AutomationDirect Productivity Suite project: L7P (software 3.11.0 (26))
author: fguedez
Rung notation: left to right = series (deeper-indented lines continue the line above), [a | b] = parallel branches, -- = plain wire, BOX.Pin = further input of the box above; 'quoted' = tag name, ? = field left empty; instruction and field names as stored in the project; options that are off are not listed.

HARDWARE
  EtherNet/IP device: Generic Client "SS2 EIP"
  Base 1 (5 slots)
    slot 0: P2-550

TAGS  (name : type @system ID = initial value)
  Dummy1 : Int16 @S16-000001
  'EC Done' : Boolean @C-000183
  'Error Counter' : Int32 @S32-000129
  'IC Done' : Boolean @C-000214
  'Interlock Counter' : Int32 @S32-000131
  'ip0001 Servo Alarm' : Int16 @S16-000021
  'ip0001N2 Servo Alarm' : Int16 @S16-000029
  'IP0009 Monitoring Parameter' : Int32 @S32-000139
  'IP0009N2 Monitoring Parameter' : Int32 @S32-000165
  'IP0010 Monitoring Parameter' : Int32 @S32-000140
  'IP0010N2 Monitoring Parameter' : Int32 @S32-000166
  'IP0011 Monitoring Parameter' : Int32 @S32-000141
  'IP0011N2 Monitoring Parameter' : Int32 @S32-000167
  'IP0012 Monitoring Parameter' : Int32 @S32-000142
  'IP0012N2 Monitoring Parameter' : Int32 @S32-000168
  'IP0013 Monitoring Parameter' : Int32 @S32-000177
  'IP0013N2 Monitoring Parameter' : Int32 @S32-000183
  'IP0025 Mapping Parameter' : Int32 @S32-000085
  'IP0025N2 Mapping Parameter' : Int32 @S32-000169
  'IP0026 Mapping Parameter' : Int32 @S32-000086
  'IP0026N2 Mapping Parameter' : Int32 @S32-000170
  'IP0027 Mapping Parameter' : Int32 @S32-000087
  'IP0027N2 Mapping Parameter' : Int32 @S32-000171
  'IP0028 Mapping Parameter' : Int32 @S32-000088
  'IP0028N2 Mapping Parameter' : Int32 @S32-000172
  'ip0046 DO Status' : Int16 @S16-000022
  'ip0046N2 DO Status' : Int16 @S16-000030
  'IP10000 Position FB' : Int32 @S32-000089
  'IP10000N2 Position Feedback' : Int32 @S32-000187
  'IP10007 Speed FB' : Int32 @S32-000091
  'IP10007N2 SpeedFeedback' : Int32 @S32-000188
  'IP10018 Z Phase offset' : Int32 @S32-000184
  'IP10018N2 Z Phase offset' : Int32 @S32-000189
  'IP10039 DI Status integrated' : Int32 @S32-000180
  'IP10039N2 DI Status integrated' : Int32 @S32-000190
  'IP10054 Torque FB' : Int32 @S32-000094
  'IP10054N2 Torque Feedback' : Int32 @S32-000191
  'ip5123 PR Status' : Int16 @S16-000028
  'ip5123N2 PR Status' : Int16 @S16-000031
  'Modbus RTU' : Boolean @C-000266
  'Modbus TCP' : Boolean @C-000304
  'OP0029 Mapping Parameter' : Int32 @S32-000099
  'OP0029N2 Mapping Parameter' : Int32 @S32-000173
  'OP0030 Mapping Parameter' : Int32 @S32-000100
  'OP0030N2 Mapping Parameter' : Int32 @S32-000174
  'OP0031 Mapping Parameter' : Int32 @S32-000101
  'OP0031N2 Mapping Parameter' : Int32 @S32-000175
  'OP0032 Mapping Parameter' : Int32 @S32-000102
  'OP0032N2 Mapping Parameter' : Int32 @S32-000176
  'OP1011 Int Speed CMD 3' : Int32 @S32-000230
  'OP1011N2 Int Speed CMD3' : Int32 @S32-000193
  'oP4007 Virtual Digital Inputs' : Int16 @S16-000007
  'oP4007N2 Virtual Digital Inputs' : Int16 @S16-000033
  'oP5112 PR Path Target' : Uint16 @US16-000013
  'oP5112N2 PR Path Target' : Int16 @S16-000034
  'oP5122 PR Path Trigger' : Uint16 @US16-000012
  'oP5122N2 PR Path Trigger' : Int16 @S16-000035
  SS2DataIn : Array[16] of Int32 @AR1S32-000001
    // element 1.2.11: warning
    // element 1.2.10: early warning for motor overload
    // element 1.2.9: homing completed
    // element 1.2.1: servo ready
    // element 1.2.2: servo activated
    // element 1.2.3: zero speed detection
    // element 1.0: Z Offset
    // element 1.2.4: target speed reached
    // element 2.0: Position Feedback
    // element 1.2.5: target position reached
    // element 1.2.6: torque limit activated
    // element 3.0: Speed Feedback
    // element 1.2.7: servo alarm
    // element 4.0: Torque Feedback
    // element 1.2.8: magnetic brake control output
    // element 5.0: DO Status
    // element 6.0: IP0025 Monitoring Parameter
    // element 7.0: IP0026 Monitoring Parameter
    // element 8.0: IP0027 Monitoring Parameter
    // element 9.0: IP0028 Monitoring Parameter
  SS2DataOut : Array[16] of Int32 @AR1S32-000002
    // element 1.1.3: PR[1]/Torque[0] sel
    // element 1.0: OP0029 Monitoring Parameter
    // element 2.0: OP0030 Monitoring Parameter
    // element 3.0: OP0031 Monitoring Parameter
    // element 4.0: OP0032 Monitoring Parameter
    // element 1.1.1: Servo Enable bit
  'Success Counter' : Int32 @S32-000130
  'Success Done' : Boolean @C-000111
  TimedC : Boolean @C-000225
  ALARM : Boolean @C-000430
  BRAKE : Boolean @C-000431
  INPOS1 : Boolean @C-000432
  INSPD : Boolean @C-000433
  READY : Boolean @C-000434
  TGON : Boolean @C-000435
  TLMT : Boolean @C-000436
  VLMT : Boolean @C-000437
  WARN : Boolean @C-000438
  ZSPD : Boolean @C-000439
  A_RST : Boolean @C-000440
  EMG : Boolean @C-000441
  GAIN2 : Boolean @C-000442
  HOME : Boolean @C-000443
  HSTART : Boolean @C-000444
  ISEL0 : Boolean @C-000445
  ISEL1 : Boolean @C-000446
  ISEL2 : Boolean @C-000447
  ISEL3 : Boolean @C-000448
  ISEL4 : Boolean @C-000449
  ISEL5 : Boolean @C-000450
  MODE : Boolean @C-000451
  N_CL : Boolean @C-000452
  NOT : Boolean @C-000453
  P_CL : Boolean @C-000454
  PAUSE : Boolean @C-000455
  PCON : Boolean @C-000456
  POT : Boolean @C-000457
  REGT : Boolean @C-000458
  RESERVED : Boolean @C-000459
  SPD1 : Boolean @C-000460
  SPD2 : Boolean @C-000461
  SPD3 : Boolean @C-000462
  START : Boolean @C-000463
  STOP : Boolean @C-000464
  SV_ON : Boolean @C-000465
  'Actual Velocity' : Int16 @S16-000036
  'Velocity Command' : Int16 @S16-000037
  'First Time' : Boolean @C-000516
  'Counter Setpoint' : Int32 @S32-000231
  'L7CA Velocity' : Boolean @C-000517
  'Actual Position' : Int32 @S32-000232
  'L7CA Index' : Boolean @C-000518
  Index : Int32 @S32-000233
  N1ALARM : Boolean @C-000577
  N1BRAKE : Boolean @C-000578
  N1INPOS1 : Boolean @C-000579
  N1INSPD : Boolean @C-000580
  N1READY : Boolean @C-000581
  N1TGON : Boolean @C-000582
  N1TLMT : Boolean @C-000583
  N1VLMT : Boolean @C-000584
  N1WARN : Boolean @C-000585
  N1ZSPD : Boolean @C-000586
  N1A_RST : Boolean @C-000587
  N1EMG : Boolean @C-000588
  N1GAIN2 : Boolean @C-000589
  N1HOME : Boolean @C-000590
  N1HSTART : Boolean @C-000591
  N1ISEL0 : Boolean @C-000592
  N1ISEL1 : Boolean @C-000593
  N1ISEL2 : Boolean @C-000594
  N1ISEL3 : Boolean @C-000595
  N1ISEL4 : Boolean @C-000596
  N1ISEL5 : Boolean @C-000597
  N1MODE : Boolean @C-000598
  N1N_CL : Boolean @C-000599
  N1NOT : Boolean @C-000600
  N1P_CL : Boolean @C-000601
  N1PAUSE : Boolean @C-000602
  N1PCON : Boolean @C-000603
  N1POT : Boolean @C-000604
  N1REGT : Boolean @C-000605
  N1RESERVED : Boolean @C-000606
  N1SPD1 : Boolean @C-000607
  N1SPD2 : Boolean @C-000608
  N1SPD3 : Boolean @C-000609
  N1START : Boolean @C-000610
  N1STOP : Boolean @C-000611
  N1SV_ON : Boolean @C-000612
  'N1Actual Velocity' : Int16 @S16-000042
  'N1Velocity Command' : Int16 @S16-000038
  N2ALARM : Boolean @C-000613
  N2BRAKE : Boolean @C-000614
  N2INPOS1 : Boolean @C-000615
  N2INSPD : Boolean @C-000616
  N2READY : Boolean @C-000617
  N2TGON : Boolean @C-000618
  N2TLMT : Boolean @C-000619
  N2VLMT : Boolean @C-000620
  N2WARN : Boolean @C-000621
  N2ZSPD : Boolean @C-000622
  N2A_RST : Boolean @C-000623
  N2EMG : Boolean @C-000624
  N2GAIN2 : Boolean @C-000625
  N2HOME : Boolean @C-000626
  N2HSTART : Boolean @C-000627
  N2ISEL0 : Boolean @C-000628
  N2ISEL1 : Boolean @C-000629
  N2ISEL2 : Boolean @C-000630
  N2ISEL3 : Boolean @C-000631
  N2ISEL4 : Boolean @C-000632
  N2ISEL5 : Boolean @C-000633
  N2MODE : Boolean @C-000634
  N2N_CL : Boolean @C-000635
  N2NOT : Boolean @C-000636
  N2P_CL : Boolean @C-000637
  N2PAUSE : Boolean @C-000638
  N2PCON : Boolean @C-000639
  N2POT : Boolean @C-000640
  N2REGT : Boolean @C-000641
  N2RESERVED : Boolean @C-000642
  N2SPD1 : Boolean @C-000643
  N2SPD2 : Boolean @C-000644
  N2SPD3 : Boolean @C-000645
  N2START : Boolean @C-000646
  N2STOP : Boolean @C-000647
  N2SV_ON : Boolean @C-000648
  'N2Actual Velocity' : Int16 @S16-000039
  'N2Velocity Command' : Int16 @S16-000040
  'L7P Velocity' : Boolean @C-000649
  'L7P Index' : Boolean @C-000650
  'N1Actual Position' : Int32 @S32-000235
  Index2 : Int16 @S16-000041
  'N2Actual Position' : Int32 @S32-000236

SYSTEM TAGS USED OR MAPPED TO MODBUS
  'L7PN1 Node Read' : MRX @SSTRUC-000048  // System Structure for Modbus Read
  'L7PN1 Node Write' : MWX @SSTRUC-000049  // System Structure for Modbus Write
  'L7PN1 Node Write2' : MWX @SSTRUC-000051  // System Structure for Modbus Write
  'L7PN2 Node Read' : MRX @SSTRUC-000053  // System Structure for Modbus Read
  'L7PN2 Node Write' : MWX @SSTRUC-000054  // System Structure for Modbus Write
  'L7PN2 Node Read2' : MRX @SSTRUC-000055  // System Structure for Modbus Read
  'L7PN2 Node Write2' : MWX @SSTRUC-000056  // System Structure for Modbus Write
  'L7PN2 Node Write3' : MWX @SSTRUC-000057  // System Structure for Modbus Write
  'L7PN1 Node Read2' : MRX @SSTRUC-000058  // System Structure for Modbus Read
  'L7PN1 Node Write3' : MWX @SSTRUC-000059  // System Structure for Modbus Write

TASK Main  (Run Every Scan)
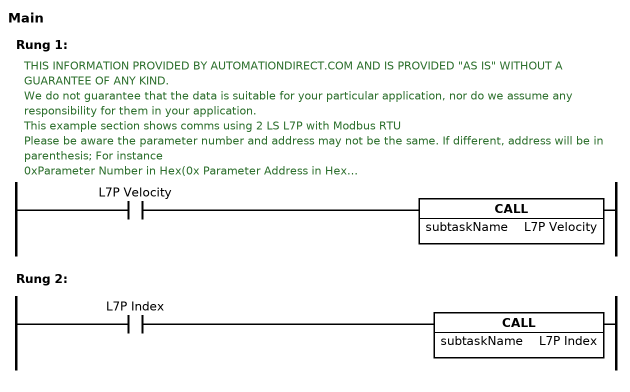
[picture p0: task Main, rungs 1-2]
Rung 1:
  // THIS INFORMATION PROVIDED BY AUTOMATIONDIRECT.COM AND IS PROVIDED "AS IS" WITHOUT A GUARANTEE OF ANY KIND.
  // We do not guarantee that the data is suitable for your particular application, nor do we assume any responsibility for them in your application.
  // This example section shows comms using 2 LS L7P with Modbus RTU
  // Please be aware the parameter number and address may not be the same. If different, address will be in parenthesis; For instance
  // 0xParameter Number in Hex(0x Parameter Address in Hex)
  // Address values are in hexadecimal
  // Please verify addresses in the LS L7P Manual
  NO('L7P Velocity') CALL('L7P Velocity')
Rung 2:
  NO('L7P Index') CALL('L7P Index')

TASK 'L7P Velocity'  (Run When Called)
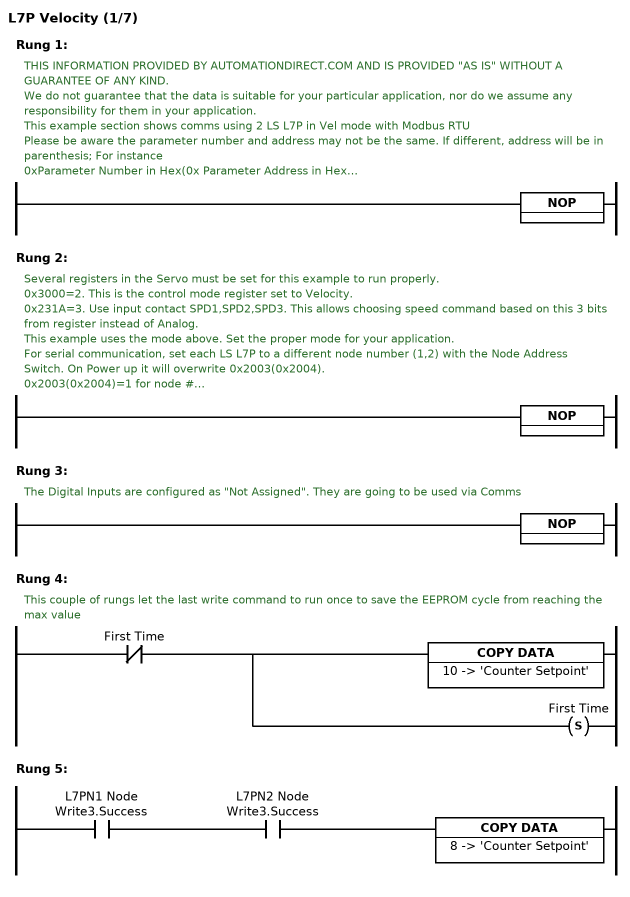
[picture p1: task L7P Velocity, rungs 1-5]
Rung 1:
  // THIS INFORMATION PROVIDED BY AUTOMATIONDIRECT.COM AND IS PROVIDED "AS IS" WITHOUT A GUARANTEE OF ANY KIND.
  // We do not guarantee that the data is suitable for your particular application, nor do we assume any responsibility for them in your application.
  // This example section shows comms using 2 LS L7P in Vel mode with Modbus RTU
  // Please be aware the parameter number and address may not be the same. If different, address will be in parenthesis; For instance
  // 0xParameter Number in Hex(0x Parameter Address in Hex)
  // Address values are in hexadecimal
  // Please verify addresses in the LS L7P Manual
  NOP()
Rung 2:
  // Several registers in the Servo must be set for this example to run properly.
  // 0x3000=2. This is the control mode register set to Velocity.
  // 0x231A=3. Use input contact SPD1,SPD2,SPD3. This allows choosing speed command based on this 3 bits from register instead of Analog.
  // This example uses the mode above. Set the proper mode for your application.
  // For serial communication, set each LS L7P to a different node number (1,2) with the Node Address Switch. On Power up it will overwrite 0x2003(0x2004).
  // 0x2003(0x2004)=1 for node #1
  // Baudrate is the same as default: 0x3002=3 [57600 bps]
  // Protocol is (8,N,1)
  // Send and Receive instructions in the PLC should use the correct node value
  NOP()
Rung 3:
  // The Digital Inputs are configured as "Not Assigned". They are going to be used via Comms
  NOP()
Rung 4:
  // This couple of rungs let the last write command to run once to save the EEPROM cycle from reaching the max value
  NC('First Time') [CPY(10 -> 'Counter Setpoint') | SET('First Time')]
Rung 5:
  NO('L7PN1 Node Write3.Success') NO('L7PN2 Node Write3.Success') CPY(8 -> 'Counter Setpoint')
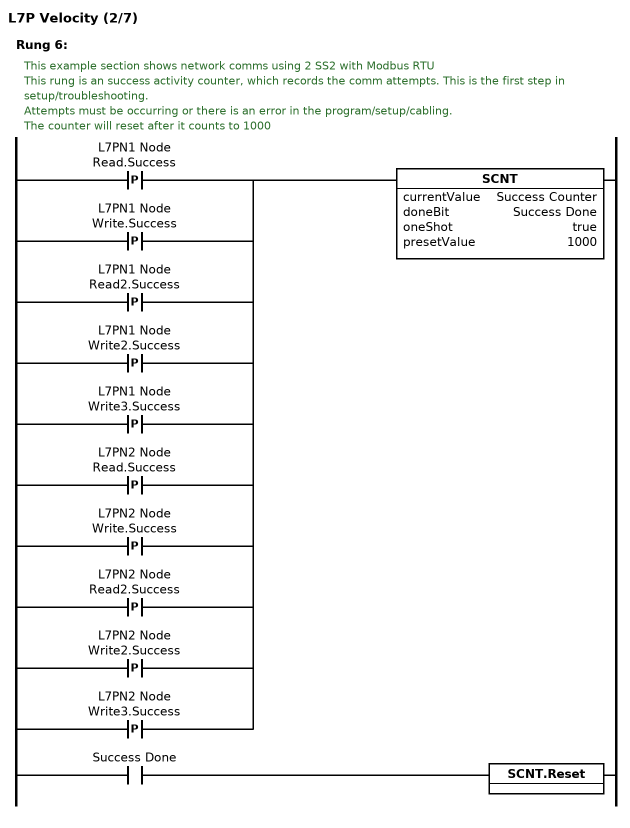
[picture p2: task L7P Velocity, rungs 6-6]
Rung 6:
  // This example section shows network comms using 2 SS2 with Modbus RTU
  // This rung is an success activity counter, which records the comm attempts. This is the first step in setup/troubleshooting.
  // Attempts must be occurring or there is an error in the program/setup/cabling.
  // The counter will reset after it counts to 1000
  [ NOE('L7PN1 Node Read.Success', rising)
    | NOE('L7PN1 Node Write.Success', rising)
    | NOE('L7PN1 Node Read2.Success', rising)
    | NOE('L7PN1 Node Write2.Success', rising)
    | NOE('L7PN1 Node Write3.Success', rising)
    | NOE('L7PN2 Node Read.Success', rising)
    | NOE('L7PN2 Node Write.Success', rising)
    | NOE('L7PN2 Node Read2.Success', rising)
    | NOE('L7PN2 Node Write2.Success', rising)
    | NOE('L7PN2 Node Write3.Success', rising) ]
    SCNT(currentValue='Success Counter', doneBit='Success Done', oneShot, presetValue=1000)
  NO('Success Done') SCNT.Reset
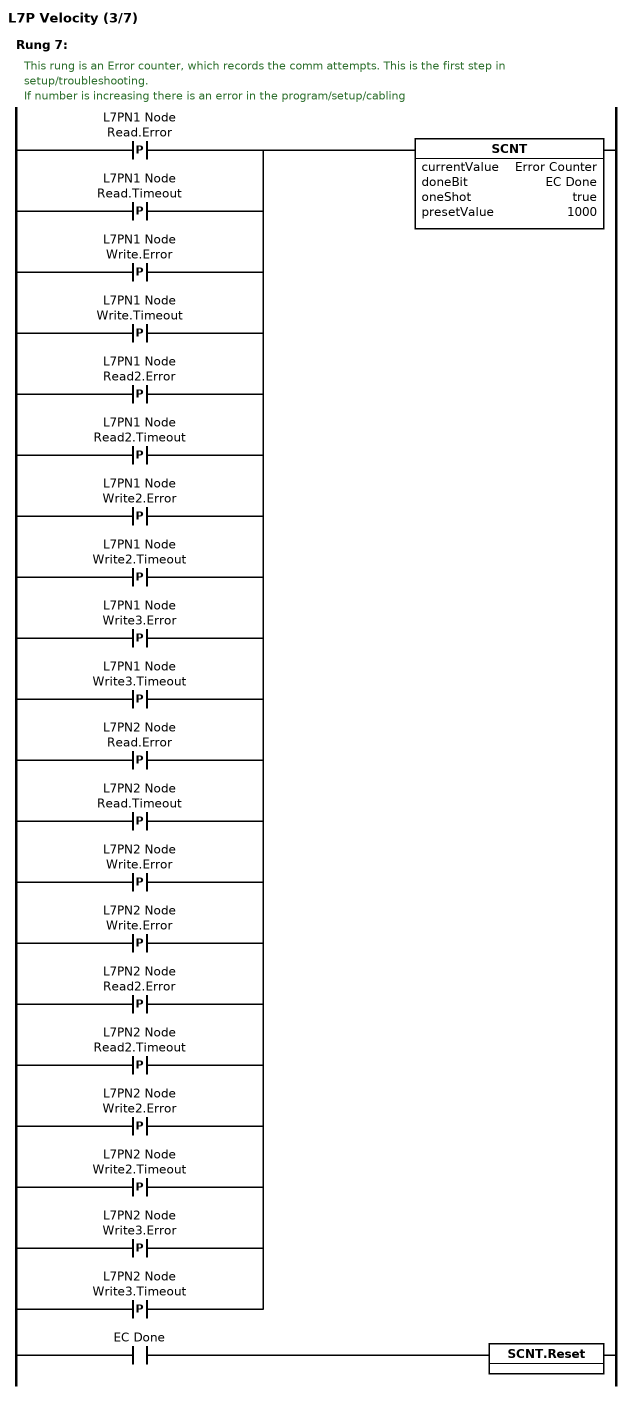
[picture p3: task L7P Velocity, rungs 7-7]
Rung 7:
  // This rung is an Error counter, which records the comm attempts. This is the first step in setup/troubleshooting.
  // If number is increasing there is an error in the program/setup/cabling
  [ NOE('L7PN1 Node Read.Error', rising)
    | NOE('L7PN1 Node Read.Timeout', rising)
    | NOE('L7PN1 Node Write.Error', rising)
    | NOE('L7PN1 Node Write.Timeout', rising)
    | NOE('L7PN1 Node Read2.Error', rising)
    | NOE('L7PN1 Node Read2.Timeout', rising)
    | NOE('L7PN1 Node Write2.Error', rising)
    | NOE('L7PN1 Node Write2.Timeout', rising)
    | NOE('L7PN1 Node Write3.Error', rising)
    | NOE('L7PN1 Node Write3.Timeout', rising)
    | NOE('L7PN2 Node Read.Error', rising)
    | NOE('L7PN2 Node Read.Timeout', rising)
    | NOE('L7PN2 Node Write.Error', rising)
    | NOE('L7PN2 Node Write.Error', rising)
    | NOE('L7PN2 Node Read2.Error', rising)
    | NOE('L7PN2 Node Read2.Timeout', rising)
    | NOE('L7PN2 Node Write2.Error', rising)
    | NOE('L7PN2 Node Write2.Timeout', rising)
    | NOE('L7PN2 Node Write3.Error', rising)
    | NOE('L7PN2 Node Write3.Timeout', rising) ]
    SCNT(currentValue='Error Counter', doneBit='EC Done', oneShot, presetValue=1000)
  NO('EC Done') SCNT.Reset
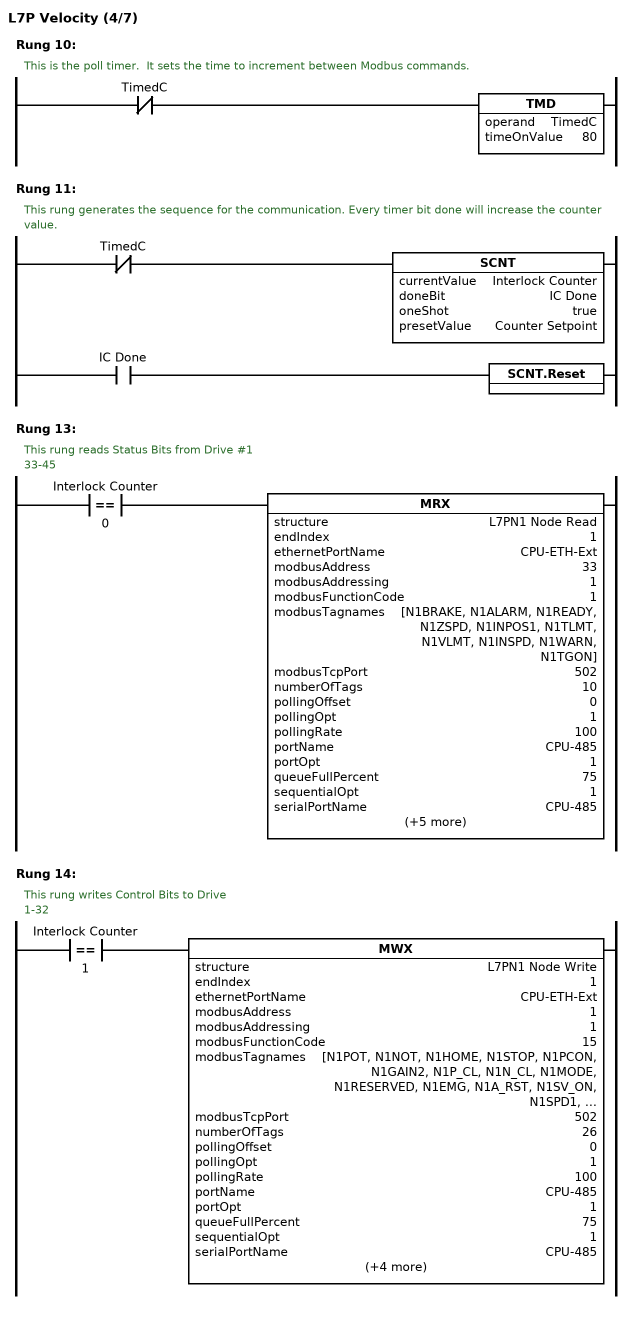
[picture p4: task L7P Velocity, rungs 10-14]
Rung 10:
  // This is the poll timer.  It sets the time to increment between Modbus commands.
  NC(TimedC) TMD(TimedC, timeOnValue=80)
Rung 11:
  // This rung generates the sequence for the communication. Every timer bit done will increase the counter value.
  NC(TimedC) SCNT(currentValue='Interlock Counter', doneBit='IC Done', oneShot, presetValue='Counter Setpoint')
  NO('IC Done') SCNT.Reset
Rung 13:
  // This rung reads Status Bits from Drive #1
  // 33-45
  COMP('Interlock Counter' = 0)
    MRX(structure='L7PN1 Node Read', endIndex=1, ethernetPortName=CPU-ETH-Ext, modbusAddress=33, modbusAddressing=1, modbusFunctionCode=1, modbusTagnames=[N1BRAKE, N1ALARM, N1READY, N1ZSPD, N1INPOS1, N1TLMT, N1VLMT, N1INSPD, N1WARN, N1TGON], modbusTcpPort=502, numberOfTags=10, pollingOffset=0, pollingOpt=1, pollingRate=100, portName=CPU-485, portOpt=1, queueFullPercent=75, sequentialOpt=1, serialPortName=CPU-485, slaveEthernetNodeNum=255, slaveSerialNodeNum=1, startingIndex=1, stringLength=2, wordSwap)
Rung 14:
  // This rung writes Control Bits to Drive
  // 1-32
  COMP('Interlock Counter' = 1)
    MWX(structure='L7PN1 Node Write', endIndex=1, ethernetPortName=CPU-ETH-Ext, modbusAddress=1, modbusAddressing=1, modbusFunctionCode=15, modbusTagnames=[N1POT, N1NOT, N1HOME, N1STOP, N1PCON, N1GAIN2, N1P_CL, N1N_CL, N1MODE, N1RESERVED, N1EMG, N1A_RST, N1SV_ON, N1SPD1, N1SPD2, N1SPD3, N1START, N1PAUSE, N1REGT, N1HSTART, N1ISEL0, N1ISEL1, N1ISEL2, N1ISEL3, N1ISEL4, N1ISEL5], modbusTcpPort=502, numberOfTags=26, pollingOffset=0, pollingOpt=1, pollingRate=100, portName=CPU-485, portOpt=1, queueFullPercent=75, sequentialOpt=1, serialPortName=CPU-485, slaveEthernetNodeNum=255, slaveSerialNodeNum=1, startingIndex=1, stringLength=2)
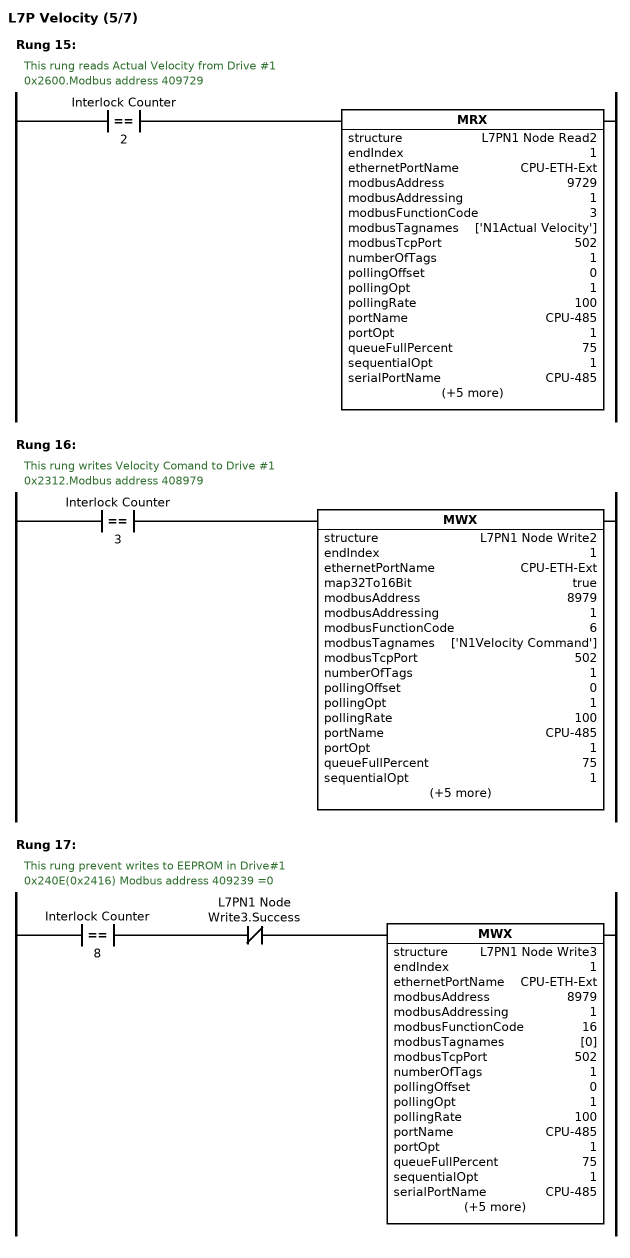
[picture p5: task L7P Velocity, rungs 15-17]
Rung 15:
  // This rung reads Actual Velocity from Drive #1
  // 0x2600.Modbus address 409729
  COMP('Interlock Counter' = 2)
    MRX(structure='L7PN1 Node Read2', endIndex=1, ethernetPortName=CPU-ETH-Ext, modbusAddress=9729, modbusAddressing=1, modbusFunctionCode=3, modbusTagnames=['N1Actual Velocity'], modbusTcpPort=502, numberOfTags=1, pollingOffset=0, pollingOpt=1, pollingRate=100, portName=CPU-485, portOpt=1, queueFullPercent=75, sequentialOpt=1, serialPortName=CPU-485, slaveEthernetNodeNum=255, slaveSerialNodeNum=1, startingIndex=1, stringLength=2, wordSwap)
Rung 16:
  // This rung writes Velocity Comand to Drive #1
  // 0x2312.Modbus address 408979
  COMP('Interlock Counter' = 3)
    MWX(structure='L7PN1 Node Write2', endIndex=1, ethernetPortName=CPU-ETH-Ext, map32To16Bit, modbusAddress=8979, modbusAddressing=1, modbusFunctionCode=6, modbusTagnames=['N1Velocity Command'], modbusTcpPort=502, numberOfTags=1, pollingOffset=0, pollingOpt=1, pollingRate=100, portName=CPU-485, portOpt=1, queueFullPercent=75, sequentialOpt=1, serialPortName=CPU-485, slaveEthernetNodeNum=255, slaveSerialNodeNum=1, startingIndex=1, stringLength=2)
Rung 17:
  // This rung prevent writes to EEPROM in Drive#1
  // 0x240E(0x2416) Modbus address 409239 =0
  COMP('Interlock Counter' = 8) NC('L7PN1 Node Write3.Success')
    MWX(structure='L7PN1 Node Write3', endIndex=1, ethernetPortName=CPU-ETH-Ext, modbusAddress=8979, modbusAddressing=1, modbusFunctionCode=16, modbusTagnames=[0], modbusTcpPort=502, numberOfTags=1, pollingOffset=0, pollingOpt=1, pollingRate=100, portName=CPU-485, portOpt=1, queueFullPercent=75, sequentialOpt=1, serialPortName=CPU-485, slaveEthernetNodeNum=255, slaveSerialNodeNum=1, startingIndex=1, stringLength=2, wordSwap)
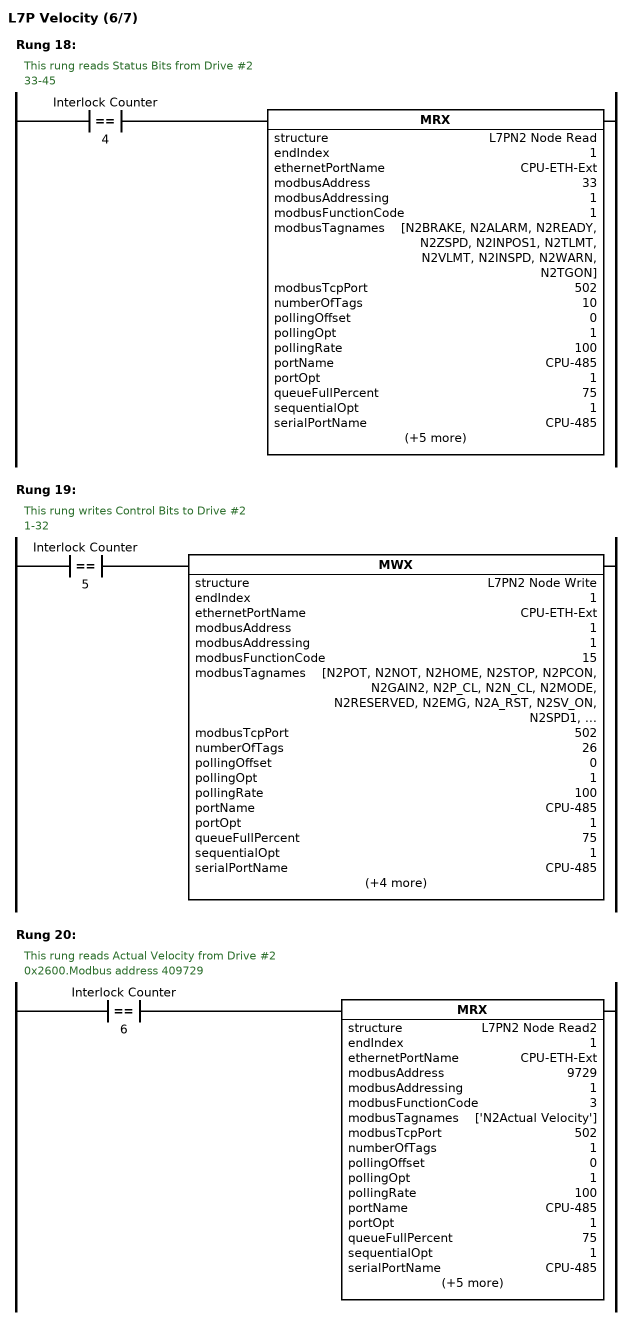
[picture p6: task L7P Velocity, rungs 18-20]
Rung 18:
  // This rung reads Status Bits from Drive #2
  // 33-45
  COMP('Interlock Counter' = 4)
    MRX(structure='L7PN2 Node Read', endIndex=1, ethernetPortName=CPU-ETH-Ext, modbusAddress=33, modbusAddressing=1, modbusFunctionCode=1, modbusTagnames=[N2BRAKE, N2ALARM, N2READY, N2ZSPD, N2INPOS1, N2TLMT, N2VLMT, N2INSPD, N2WARN, N2TGON], modbusTcpPort=502, numberOfTags=10, pollingOffset=0, pollingOpt=1, pollingRate=100, portName=CPU-485, portOpt=1, queueFullPercent=75, sequentialOpt=1, serialPortName=CPU-485, slaveEthernetNodeNum=255, slaveSerialNodeNum=2, startingIndex=1, stringLength=2, wordSwap)
Rung 19:
  // This rung writes Control Bits to Drive #2
  // 1-32
  COMP('Interlock Counter' = 5)
    MWX(structure='L7PN2 Node Write', endIndex=1, ethernetPortName=CPU-ETH-Ext, modbusAddress=1, modbusAddressing=1, modbusFunctionCode=15, modbusTagnames=[N2POT, N2NOT, N2HOME, N2STOP, N2PCON, N2GAIN2, N2P_CL, N2N_CL, N2MODE, N2RESERVED, N2EMG, N2A_RST, N2SV_ON, N2SPD1, N2SPD2, N2SPD3, N2START, N2PAUSE, N2REGT, N2HSTART, N2ISEL0, N2ISEL1, N2ISEL2, N2ISEL3, N2ISEL4, N2ISEL5], modbusTcpPort=502, numberOfTags=26, pollingOffset=0, pollingOpt=1, pollingRate=100, portName=CPU-485, portOpt=1, queueFullPercent=75, sequentialOpt=1, serialPortName=CPU-485, slaveEthernetNodeNum=255, slaveSerialNodeNum=2, startingIndex=1, stringLength=2)
Rung 20:
  // This rung reads Actual Velocity from Drive #2
  // 0x2600.Modbus address 409729
  COMP('Interlock Counter' = 6)
    MRX(structure='L7PN2 Node Read2', endIndex=1, ethernetPortName=CPU-ETH-Ext, modbusAddress=9729, modbusAddressing=1, modbusFunctionCode=3, modbusTagnames=['N2Actual Velocity'], modbusTcpPort=502, numberOfTags=1, pollingOffset=0, pollingOpt=1, pollingRate=100, portName=CPU-485, portOpt=1, queueFullPercent=75, sequentialOpt=1, serialPortName=CPU-485, slaveEthernetNodeNum=255, slaveSerialNodeNum=2, startingIndex=1, stringLength=2, wordSwap)
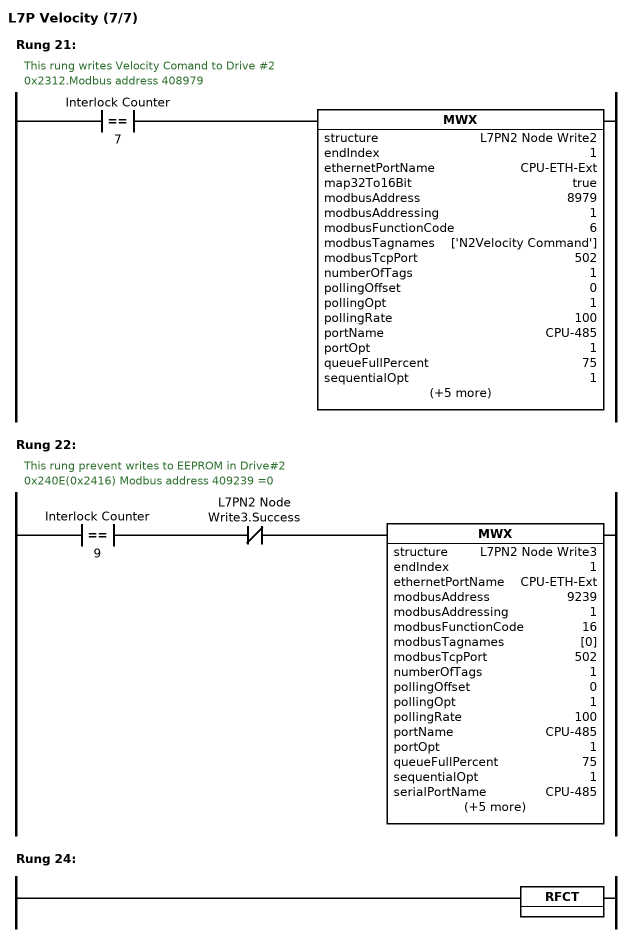
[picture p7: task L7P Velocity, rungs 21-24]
Rung 21:
  // This rung writes Velocity Comand to Drive #2
  // 0x2312.Modbus address 408979
  COMP('Interlock Counter' = 7)
    MWX(structure='L7PN2 Node Write2', endIndex=1, ethernetPortName=CPU-ETH-Ext, map32To16Bit, modbusAddress=8979, modbusAddressing=1, modbusFunctionCode=6, modbusTagnames=['N2Velocity Command'], modbusTcpPort=502, numberOfTags=1, pollingOffset=0, pollingOpt=1, pollingRate=100, portName=CPU-485, portOpt=1, queueFullPercent=75, sequentialOpt=1, serialPortName=CPU-485, slaveEthernetNodeNum=255, slaveSerialNodeNum=2, startingIndex=1, stringLength=2)
Rung 22:
  // This rung prevent writes to EEPROM in Drive#2
  // 0x240E(0x2416) Modbus address 409239 =0
  COMP('Interlock Counter' = 9) NC('L7PN2 Node Write3.Success')
    MWX(structure='L7PN2 Node Write3', endIndex=1, ethernetPortName=CPU-ETH-Ext, modbusAddress=9239, modbusAddressing=1, modbusFunctionCode=16, modbusTagnames=[0], modbusTcpPort=502, numberOfTags=1, pollingOffset=0, pollingOpt=1, pollingRate=100, portName=CPU-485, portOpt=1, queueFullPercent=75, sequentialOpt=1, serialPortName=CPU-485, slaveEthernetNodeNum=255, slaveSerialNodeNum=2, startingIndex=1, stringLength=2, wordSwap)
Rung 24:
  RFCT()

TASK 'L7P Index'  (Run When Called)
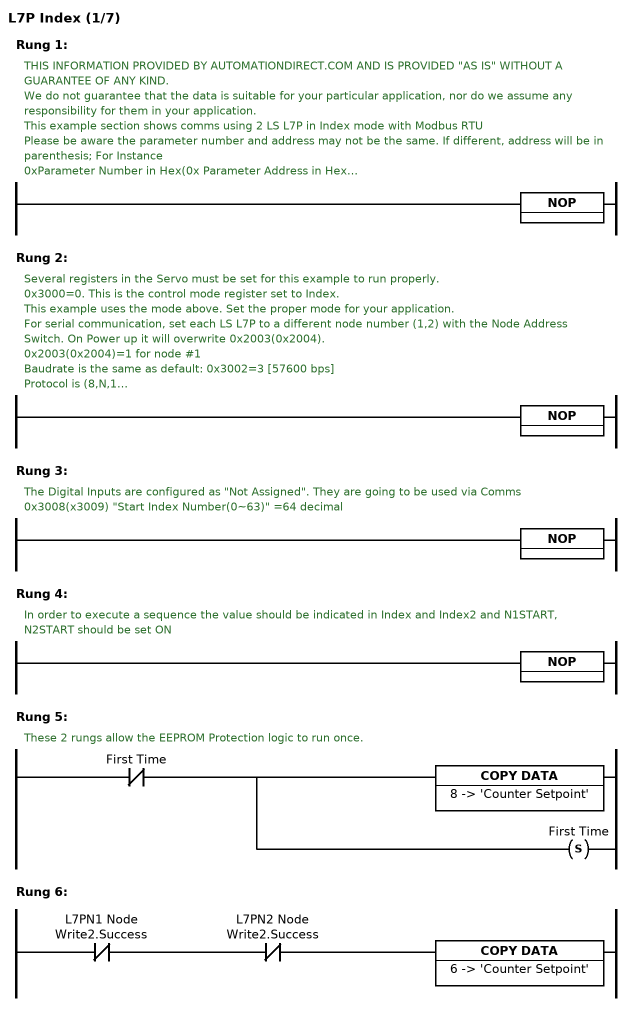
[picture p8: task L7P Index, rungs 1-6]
Rung 1:
  // THIS INFORMATION PROVIDED BY AUTOMATIONDIRECT.COM AND IS PROVIDED "AS IS" WITHOUT A GUARANTEE OF ANY KIND.
  // We do not guarantee that the data is suitable for your particular application, nor do we assume any responsibility for them in your application.
  // This example section shows comms using 2 LS L7P in Index mode with Modbus RTU
  // Please be aware the parameter number and address may not be the same. If different, address will be in parenthesis; For Instance
  // 0xParameter Number in Hex(0x Parameter Address in Hex)
  // Address values are in hexadecimal
  // Please verify addresses in the LS L7P Manual
  NOP()
Rung 2:
  // Several registers in the Servo must be set for this example to run properly.
  // 0x3000=0. This is the control mode register set to Index.
  // This example uses the mode above. Set the proper mode for your application.
  // For serial communication, set each LS L7P to a different node number (1,2) with the Node Address Switch. On Power up it will overwrite 0x2003(0x2004).
  // 0x2003(0x2004)=1 for node #1
  // Baudrate is the same as default: 0x3002=3 [57600 bps]
  // Protocol is (8,N,1)
  // Send and Receive instructions in the PLC should use the correct node value
  NOP()
Rung 3:
  // The Digital Inputs are configured as "Not Assigned". They are going to be used via Comms
  // 0x3008(x3009) "Start Index Number(0~63)" =64 decimal
  NOP()
Rung 4:
  // In order to execute a sequence the value should be indicated in Index and Index2 and N1START, N2START should be set ON
  NOP()
Rung 5:
  // These 2 rungs allow the EEPROM Protection logic to run once.
  NC('First Time') [CPY(8 -> 'Counter Setpoint') | SET('First Time')]
Rung 6:
  NC('L7PN1 Node Write2.Success') NC('L7PN2 Node Write2.Success') CPY(6 -> 'Counter Setpoint')
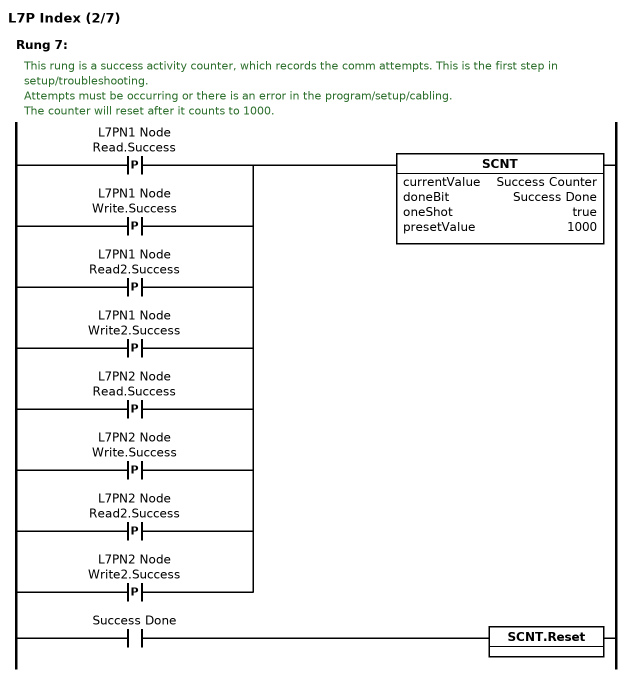
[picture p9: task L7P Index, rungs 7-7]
Rung 7:
  // This rung is a success activity counter, which records the comm attempts. This is the first step in setup/troubleshooting.
  // Attempts must be occurring or there is an error in the program/setup/cabling.
  // The counter will reset after it counts to 1000.
  [ NOE('L7PN1 Node Read.Success', rising)
    | NOE('L7PN1 Node Write.Success', rising)
    | NOE('L7PN1 Node Read2.Success', rising)
    | NOE('L7PN1 Node Write2.Success', rising)
    | NOE('L7PN2 Node Read.Success', rising)
    | NOE('L7PN2 Node Write.Success', rising)
    | NOE('L7PN2 Node Read2.Success', rising)
    | NOE('L7PN2 Node Write2.Success', rising) ]
    SCNT(currentValue='Success Counter', doneBit='Success Done', oneShot, presetValue=1000)
  NO('Success Done') SCNT.Reset
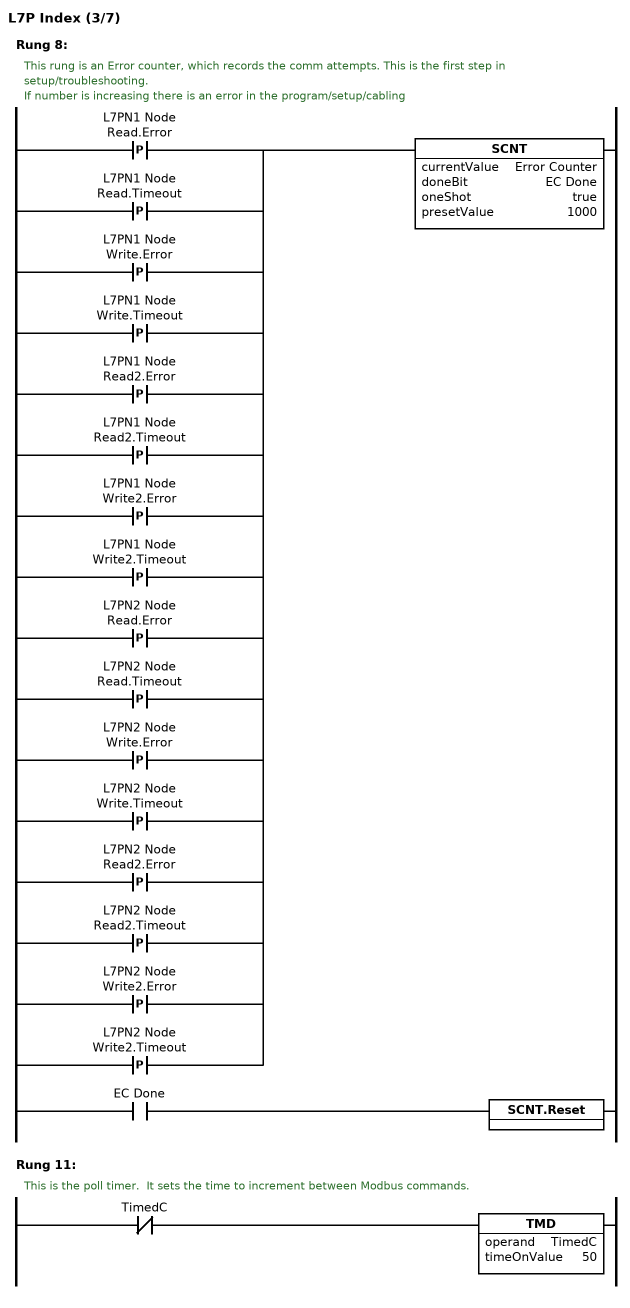
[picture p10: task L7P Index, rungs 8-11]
Rung 8:
  // This rung is an Error counter, which records the comm attempts. This is the first step in setup/troubleshooting.
  // If number is increasing there is an error in the program/setup/cabling
  [ NOE('L7PN1 Node Read.Error', rising)
    | NOE('L7PN1 Node Read.Timeout', rising)
    | NOE('L7PN1 Node Write.Error', rising)
    | NOE('L7PN1 Node Write.Timeout', rising)
    | NOE('L7PN1 Node Read2.Error', rising)
    | NOE('L7PN1 Node Read2.Timeout', rising)
    | NOE('L7PN1 Node Write2.Error', rising)
    | NOE('L7PN1 Node Write2.Timeout', rising)
    | NOE('L7PN2 Node Read.Error', rising)
    | NOE('L7PN2 Node Read.Timeout', rising)
    | NOE('L7PN2 Node Write.Error', rising)
    | NOE('L7PN2 Node Write.Timeout', rising)
    | NOE('L7PN2 Node Read2.Error', rising)
    | NOE('L7PN2 Node Read2.Timeout', rising)
    | NOE('L7PN2 Node Write2.Error', rising)
    | NOE('L7PN2 Node Write2.Timeout', rising) ]
    SCNT(currentValue='Error Counter', doneBit='EC Done', oneShot, presetValue=1000)
  NO('EC Done') SCNT.Reset
Rung 11:
  // This is the poll timer.  It sets the time to increment between Modbus commands.
  NC(TimedC) TMD(TimedC, timeOnValue=50)
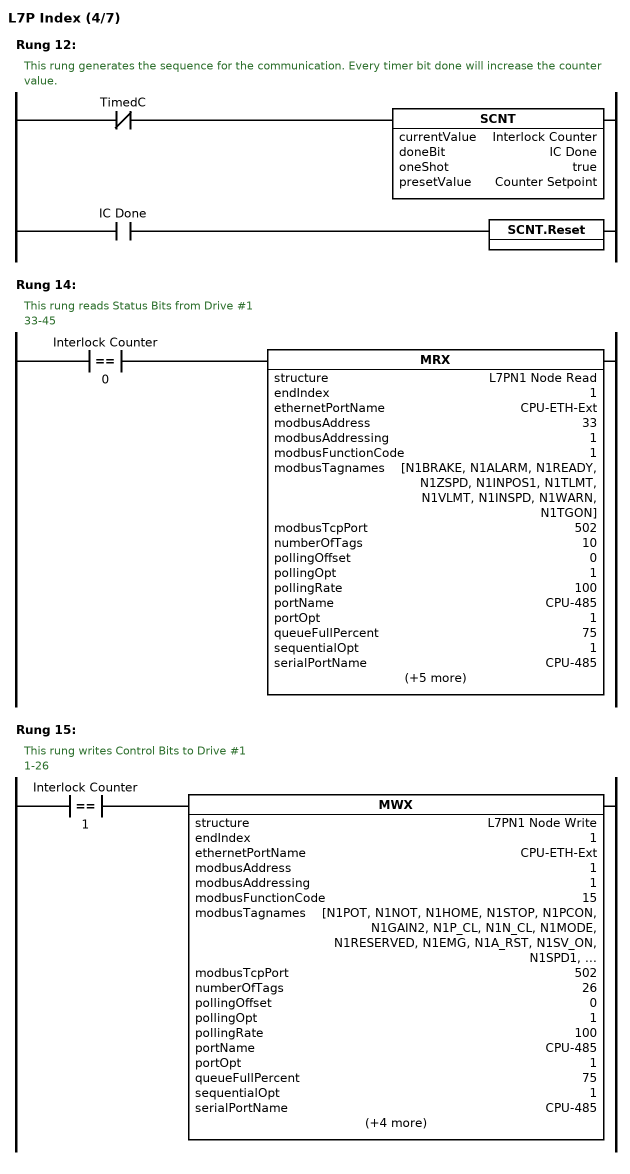
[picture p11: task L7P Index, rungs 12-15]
Rung 12:
  // This rung generates the sequence for the communication. Every timer bit done will increase the counter value.
  NC(TimedC) SCNT(currentValue='Interlock Counter', doneBit='IC Done', oneShot, presetValue='Counter Setpoint')
  NO('IC Done') SCNT.Reset
Rung 14:
  // This rung reads Status Bits from Drive #1
  // 33-45
  COMP('Interlock Counter' = 0)
    MRX(structure='L7PN1 Node Read', endIndex=1, ethernetPortName=CPU-ETH-Ext, modbusAddress=33, modbusAddressing=1, modbusFunctionCode=1, modbusTagnames=[N1BRAKE, N1ALARM, N1READY, N1ZSPD, N1INPOS1, N1TLMT, N1VLMT, N1INSPD, N1WARN, N1TGON], modbusTcpPort=502, numberOfTags=10, pollingOffset=0, pollingOpt=1, pollingRate=100, portName=CPU-485, portOpt=1, queueFullPercent=75, sequentialOpt=1, serialPortName=CPU-485, slaveEthernetNodeNum=255, slaveSerialNodeNum=1, startingIndex=1, stringLength=2, wordSwap)
Rung 15:
  // This rung writes Control Bits to Drive #1
  // 1-26
  COMP('Interlock Counter' = 1)
    MWX(structure='L7PN1 Node Write', endIndex=1, ethernetPortName=CPU-ETH-Ext, modbusAddress=1, modbusAddressing=1, modbusFunctionCode=15, modbusTagnames=[N1POT, N1NOT, N1HOME, N1STOP, N1PCON, N1GAIN2, N1P_CL, N1N_CL, N1MODE, N1RESERVED, N1EMG, N1A_RST, N1SV_ON, N1SPD1, N1SPD2, N1SPD3, N1START, N1PAUSE, N1REGT, N1HSTART, N1ISEL0, N1ISEL1, N1ISEL2, N1ISEL3, N1ISEL4, N1ISEL5], modbusTcpPort=502, numberOfTags=26, pollingOffset=0, pollingOpt=1, pollingRate=100, portName=CPU-485, portOpt=1, queueFullPercent=75, sequentialOpt=1, serialPortName=CPU-485, slaveEthernetNodeNum=255, slaveSerialNodeNum=1, startingIndex=1, stringLength=2)
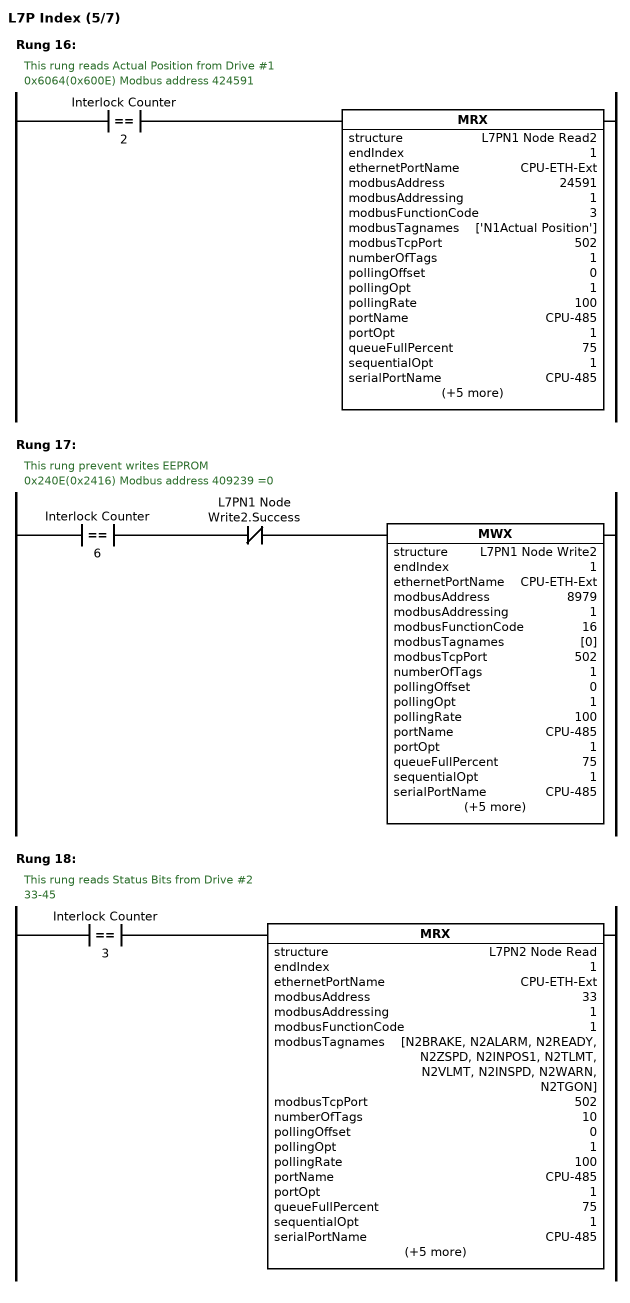
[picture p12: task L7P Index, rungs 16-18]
Rung 16:
  // This rung reads Actual Position from Drive #1
  // 0x6064(0x600E) Modbus address 424591
  COMP('Interlock Counter' = 2)
    MRX(structure='L7PN1 Node Read2', endIndex=1, ethernetPortName=CPU-ETH-Ext, modbusAddress=24591, modbusAddressing=1, modbusFunctionCode=3, modbusTagnames=['N1Actual Position'], modbusTcpPort=502, numberOfTags=1, pollingOffset=0, pollingOpt=1, pollingRate=100, portName=CPU-485, portOpt=1, queueFullPercent=75, sequentialOpt=1, serialPortName=CPU-485, slaveEthernetNodeNum=255, slaveSerialNodeNum=1, startingIndex=1, stringLength=2, wordSwap)
Rung 17:
  // This rung prevent writes EEPROM
  // 0x240E(0x2416) Modbus address 409239 =0
  COMP('Interlock Counter' = 6) NC('L7PN1 Node Write2.Success')
    MWX(structure='L7PN1 Node Write2', endIndex=1, ethernetPortName=CPU-ETH-Ext, modbusAddress=8979, modbusAddressing=1, modbusFunctionCode=16, modbusTagnames=[0], modbusTcpPort=502, numberOfTags=1, pollingOffset=0, pollingOpt=1, pollingRate=100, portName=CPU-485, portOpt=1, queueFullPercent=75, sequentialOpt=1, serialPortName=CPU-485, slaveEthernetNodeNum=255, slaveSerialNodeNum=1, startingIndex=1, stringLength=2, wordSwap)
Rung 18:
  // This rung reads Status Bits from Drive #2
  // 33-45
  COMP('Interlock Counter' = 3)
    MRX(structure='L7PN2 Node Read', endIndex=1, ethernetPortName=CPU-ETH-Ext, modbusAddress=33, modbusAddressing=1, modbusFunctionCode=1, modbusTagnames=[N2BRAKE, N2ALARM, N2READY, N2ZSPD, N2INPOS1, N2TLMT, N2VLMT, N2INSPD, N2WARN, N2TGON], modbusTcpPort=502, numberOfTags=10, pollingOffset=0, pollingOpt=1, pollingRate=100, portName=CPU-485, portOpt=1, queueFullPercent=75, sequentialOpt=1, serialPortName=CPU-485, slaveEthernetNodeNum=255, slaveSerialNodeNum=2, startingIndex=1, stringLength=2, wordSwap)
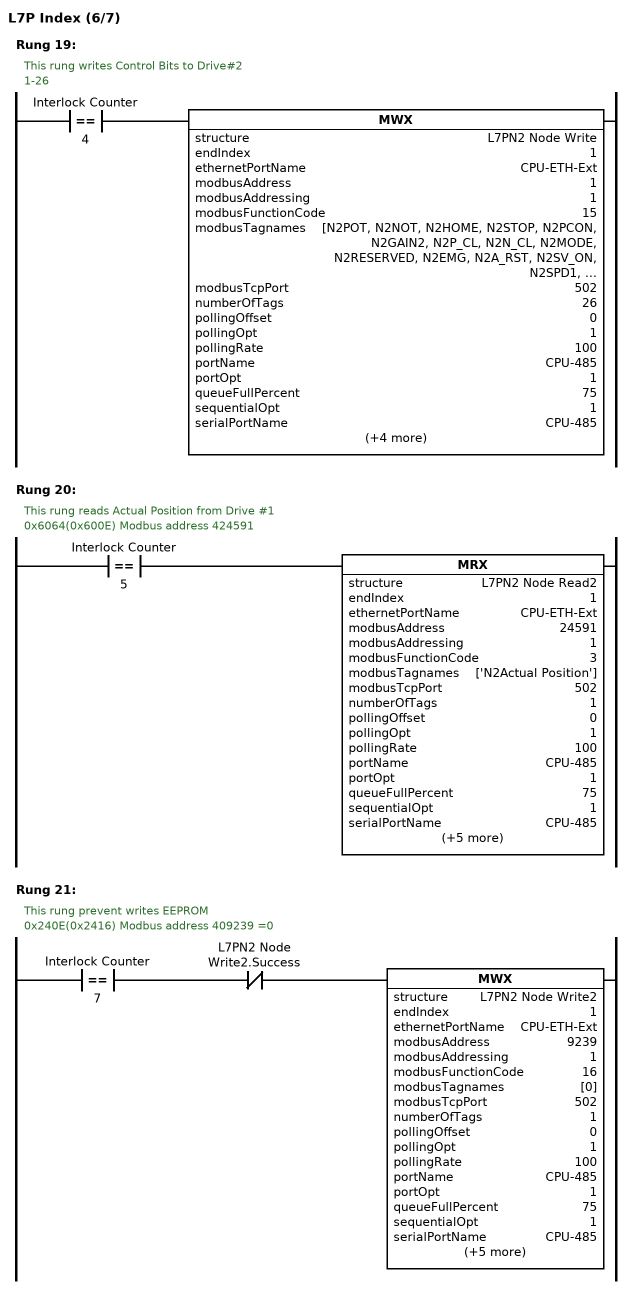
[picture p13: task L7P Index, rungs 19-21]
Rung 19:
  // This rung writes Control Bits to Drive#2
  // 1-26
  COMP('Interlock Counter' = 4)
    MWX(structure='L7PN2 Node Write', endIndex=1, ethernetPortName=CPU-ETH-Ext, modbusAddress=1, modbusAddressing=1, modbusFunctionCode=15, modbusTagnames=[N2POT, N2NOT, N2HOME, N2STOP, N2PCON, N2GAIN2, N2P_CL, N2N_CL, N2MODE, N2RESERVED, N2EMG, N2A_RST, N2SV_ON, N2SPD1, N2SPD2, N2SPD3, N2START, N2PAUSE, N2REGT, N2HSTART, N2ISEL0, N2ISEL1, N2ISEL2, N2ISEL3, N2ISEL4, N2ISEL5], modbusTcpPort=502, numberOfTags=26, pollingOffset=0, pollingOpt=1, pollingRate=100, portName=CPU-485, portOpt=1, queueFullPercent=75, sequentialOpt=1, serialPortName=CPU-485, slaveEthernetNodeNum=255, slaveSerialNodeNum=2, startingIndex=1, stringLength=2)
Rung 20:
  // This rung reads Actual Position from Drive #1
  // 0x6064(0x600E) Modbus address 424591
  COMP('Interlock Counter' = 5)
    MRX(structure='L7PN2 Node Read2', endIndex=1, ethernetPortName=CPU-ETH-Ext, modbusAddress=24591, modbusAddressing=1, modbusFunctionCode=3, modbusTagnames=['N2Actual Position'], modbusTcpPort=502, numberOfTags=1, pollingOffset=0, pollingOpt=1, pollingRate=100, portName=CPU-485, portOpt=1, queueFullPercent=75, sequentialOpt=1, serialPortName=CPU-485, slaveEthernetNodeNum=255, slaveSerialNodeNum=2, startingIndex=1, stringLength=2, wordSwap)
Rung 21:
  // This rung prevent writes EEPROM
  // 0x240E(0x2416) Modbus address 409239 =0
  COMP('Interlock Counter' = 7) NC('L7PN2 Node Write2.Success')
    MWX(structure='L7PN2 Node Write2', endIndex=1, ethernetPortName=CPU-ETH-Ext, modbusAddress=9239, modbusAddressing=1, modbusFunctionCode=16, modbusTagnames=[0], modbusTcpPort=502, numberOfTags=1, pollingOffset=0, pollingOpt=1, pollingRate=100, portName=CPU-485, portOpt=1, queueFullPercent=75, sequentialOpt=1, serialPortName=CPU-485, slaveEthernetNodeNum=255, slaveSerialNodeNum=2, startingIndex=1, stringLength=2, wordSwap)
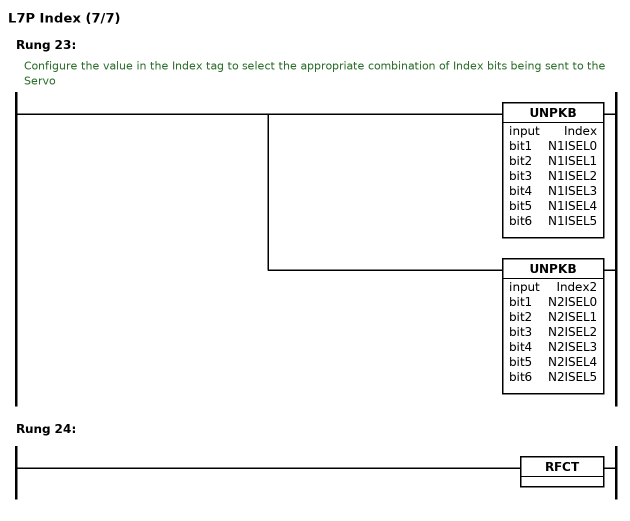
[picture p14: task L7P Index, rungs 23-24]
Rung 23:
  // Configure the value in the Index tag to select the appropriate combination of Index bits being sent to the Servo
  UNPKB(input=Index, bit1=N1ISEL0, bit2=N1ISEL1, bit3=N1ISEL2, bit4=N1ISEL3, bit5=N1ISEL4, bit6=N1ISEL5)
  UNPKB(input=Index2, bit1=N2ISEL0, bit2=N2ISEL1, bit3=N2ISEL2, bit4=N2ISEL3, bit5=N2ISEL4, bit6=N2ISEL5)
Rung 24:
  RFCT()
